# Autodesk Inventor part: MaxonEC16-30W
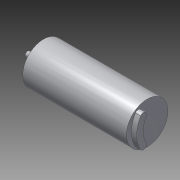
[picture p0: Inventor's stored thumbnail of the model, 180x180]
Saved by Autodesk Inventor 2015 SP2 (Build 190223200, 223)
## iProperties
Created: 2012-07
Part Number: MaxonEC16-30W
Material: Titan
Document SubType Name: Modeling
Designer: rYan
Mass: 36.7331 g
Surface Area: 25.9963 cm^2
Volume: 8.1448 cm^3
Density: 4.51 g/cm^3
Appearance: Glatt - weiß
Author: rYan
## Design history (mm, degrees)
sketch "Skizze1"
  geometry: L1 (-23.05, 0)-(-23.05, 1); L2 (-23.05, 1)-(-17.95, 1); L3 (-17.95, 1)-(-17.95, 4.5); L4 (-17.95, 4.5)-(-16.95, 4.5); L5 (-16.95, 4.5)-(-16.95, 8); L6 (-16.95, 8)-(23.05, 8); L7 (23.05, 8)-(23.05, 0); L8 (23.05, 0)-(-23.05, 0); L9 (0, 9.6)-(0, -1.6) reference; L10 (-32.27, 0)-(32.27, 0) reference; 1 further point
  constraints: 16 end point, 6 parallel, 1 collinear, 1 perpendicular, 1 vertical, 1 other
  dimensions: "d1" = 2 diameter of L2 L8; "d3" = 9 diameter of L4 L8; "d4" = 16 diameter of L6 L8; "d6" = 6.1 distance between parallel lines of L5 L1; "d7" = 1 distance between parallel lines of L5 L3; "d8" = 40 distance between parallel lines of L7 L5
revolve "Umdrehung1" sketch "Skizze1" stored, may be unused: angle "d9" = 90 deg
sketch "Skizze2"
  geometry: C1 r 4.5 at (0, 0) reference; 2 further points
  constraints: 1 coincident
hole "Bohrung1" sketch "Skizze2" at (0, 0) diameter "d10" = 7; stored, may be unused: countersink angle "d14" = 90 deg, drill point angle "d16" = 0 deg; dims "d11" = 6, "d12" = 4, "d13" = 2, "d15" = 0.5
sketch "Skizze3"
  geometry: L1 (-11.2, 0)-(11.2, 0) reference; L2 (0, -11.2)-(0, 11.2) reference; A1 r 8.75 centre (0, 5.2) between (-4.375, -2.378) and (4.375, -2.378); A2 r 1.25 centre (-5, -3.46) between (-4.375, -2.378) and (-5.625, -4.543); A3 r 1.25 centre (5, -3.46) between (5.625, -4.543) and (4.375, -2.378); A4 r 11.25 centre (0, 5.2) between (-5.625, -4.543) and (5.625, -4.543)
  constraints: 8 point on circle, 4 centre point, 4 tangent, 1 point on line, 1 symmetric about line
  dimensions: "d19" = 8.75 radius of A1; "d20" = 11.25 radius of A4; "d21" = 5.2 distance from line of L1 A1.centre; "d22" = 10 distance of A3.centre A2.centre; "d23" = 1.25 radius of A3
extrude "Extrusion1" join sketch "Skizze3" distance "d24" = 2; taper "d25" = 0 deg
sketch "Skizze4" dims "d26" = 11
  geometry: L1 (-11.2, 0)-(11.2, 0) reference; L2 (0, 11.2)-(0, -11.2) reference; C1 r 8 at (0, 0) reference; 3 further points
  constraints: 1 coincident, 1 point on line, 1 vertical alignment, 2 other
hole "Bohrung2" sketch "Skizze4" at (0, 5.5) diameter "d28" = 1.567; stored, may be unused: countersink angle "d32" = 90 deg, drill point angle "d34" = 0 deg; dims "d29" = 6, "d30" = 4, "d31" = 2, "d33" = 3.5
pattern_circular "Runde Anordnung1" dims angle "d36" = 360 deg
node "Volumenkörper1"
